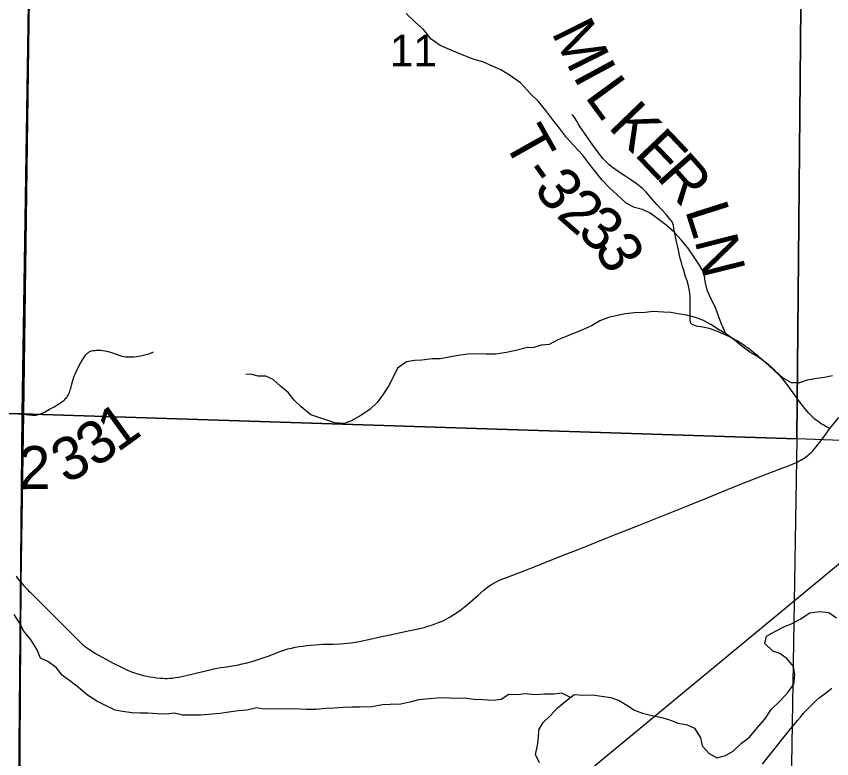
# Model space of a CAD drawing. Extents: x 0 to 34, y 0 to 22.
# Drawn here: x 3.363 to 4.44, y 19.271 to 20.252 of the extents above; entities that cross this region are included whole.
import ezdxf

# ---------------------------------------------------------------- set-up
doc = ezdxf.new("R2010")
doc.units = 0
for name, color, linetype in [('GM_X_Corporation', 7, 'Continuous'), ('GM_X_County_Road', 7, 'Continuous'), ('GM_X_Minor_River', 7, 'Continuous'), ('GM_X_Rail_Line', 7, 'Continuous'), ('GM_X_Section_Text', 7, 'Continuous'), ('GM_X_State_Route', 7, 'Continuous'), ('GM_X_Township_Road', 7, 'Continuous'), ('GM_X_Township_Road_Text', 7, 'Continuous')]:
    doc.layers.add(name, color=color, linetype=linetype)

msp = doc.modelspace()

# ---------------------------------------------------------------- linework, layer by layer
at = {"layer": 'GM_X_Corporation'}
for points in [[(5.3543, 16.3597), (5.3699, 17.5116), (5.3717, 17.6123), (4.6401, 17.6298), (4.3705, 17.6391), (4.3669, 17.8198), (4.37, 17.9048), (4.3768, 18.4091), (4.3782, 18.6502), (4.377, 18.6713), (3.7035, 18.69), (3.3642, 18.7005), (3.3691, 19.5041), (3.3724, 19.7263), (3.3869, 20.7918), (3.3886, 20.9), (2.1, 20.9), (2.1, 15.6606)], [(8.9, 20.9), (3.3886, 20.9), (3.3869, 20.7918), (3.3724, 19.7263), (3.3691, 19.5041), (3.3642, 18.7005)]]:
    msp.add_lwpolyline(points, dxfattribs=at)
for points in [[(3.3867, 20.754), (3.3708, 19.7265), (2.3578, 19.7506), (2.3781, 20.7796)], [(3.3867, 20.754), (4.4032, 20.6929), (4.3939, 19.6935), (3.3708, 19.7265)], [(5.4344, 20.6525), (5.4328, 20.6183), (5.4095, 19.6556), (4.3939, 19.6935), (4.4032, 20.6929)], [(3.3708, 19.7265), (3.3614, 18.7006), (2.3352, 18.7231), (2.3578, 19.7506)], [(4.3939, 19.6935), (4.3772, 18.6714), (3.3614, 18.7006), (3.3708, 19.7265)]]:
    msp.add_lwpolyline(points, close=True, dxfattribs=at)
at = {"layer": 'GM_X_County_Road'}
for points in [[(4.4377, 19.7069), (4.4493, 19.7218)], [(3.3693, 19.5036), (3.371, 19.5016), (3.3725, 19.4998), (3.3739, 19.4983), (3.3755, 19.4966), (3.3767, 19.4953), (3.378, 19.494), (3.3791, 19.4928), (3.3811, 19.4908), (3.3864, 19.4856), (3.3959, 19.4764), (3.4114, 19.461), (3.4372, 19.435), (3.4451, 19.427), (3.4501, 19.4224), (3.4523, 19.4205), (3.4545, 19.4188), (3.4568, 19.417), (3.4595, 19.4151), (3.463, 19.4128), (3.4669, 19.4104), (3.4771, 19.4045), (3.4908, 19.3971), (3.5036, 19.3908), (3.5109, 19.3874), (3.515, 19.3858), (3.5191, 19.3843), (3.522, 19.3833), (3.5267, 19.382), (3.5309, 19.3808), (3.5354, 19.3798), (3.5394, 19.3791), (3.5438, 19.3784), (3.5488, 19.3778), (3.5529, 19.3774), (3.5564, 19.3772), (3.5594, 19.377), (3.5622, 19.3769), (3.5656, 19.3771), (3.5691, 19.3774), (3.5732, 19.378), (3.5777, 19.3788), (3.5929, 19.3823), (3.6038, 19.3849), (3.6098, 19.3863), (3.6186, 19.3884), (3.6237, 19.3895), (3.6284, 19.3904), (3.6332, 19.3912), (3.6377, 19.3919), (3.6407, 19.3923), (3.6437, 19.3928), (3.648, 19.3935), (3.6517, 19.3941), (3.6564, 19.395), (3.6614, 19.396), (3.6662, 19.3971), (3.6711, 19.3984), (3.6746, 19.3993), (3.6783, 19.4005), (3.6836, 19.4022), (3.6889, 19.4041), (3.6968, 19.407), (3.7046, 19.41), (3.7122, 19.4128), (3.7166, 19.4144), (3.719, 19.4152), (3.7215, 19.4159), (3.724, 19.4165), (3.7264, 19.4171), (3.7313, 19.4181), (3.7366, 19.419), (3.7415, 19.4197), (3.7469, 19.4204), (3.7519, 19.421), (3.7572, 19.4214), (3.7626, 19.4217), (3.7684, 19.422), (3.7752, 19.4222), (3.7814, 19.4224), (3.7907, 19.4227), (3.7954, 19.423), (3.8001, 19.4233), (3.8047, 19.4238), (3.808, 19.4242), (3.8107, 19.4247), (3.8134, 19.4251), (3.8164, 19.4257), (3.8199, 19.4265), (3.8282, 19.4283), (3.8436, 19.4317), (3.8544, 19.4341), (3.8649, 19.4364), (3.8826, 19.4401), (3.896, 19.443), (3.9015, 19.4444), (3.9067, 19.4458), (3.9128, 19.4478), (3.9173, 19.4495), (3.9215, 19.4511), (3.9253, 19.4527), (3.9288, 19.4544), (3.9323, 19.4562), (3.9361, 19.4583), (3.9431, 19.4625), (3.9502, 19.4675), (3.959, 19.4746), (3.973, 19.487), (3.9804, 19.4935), (3.9838, 19.4963), (3.987, 19.4986), (3.9894, 19.5003), (3.9918, 19.5017), (3.9946, 19.5034), (3.9978, 19.505), (4.0005, 19.5062), (4.0034, 19.5075), (4.012, 19.5109), (4.0266, 19.5163), (4.0463, 19.524), (4.0623, 19.5305), (4.0808, 19.5379), (4.1051, 19.5474), (4.1207, 19.5536), (4.142, 19.5622), (4.1553, 19.5675), (4.1813, 19.5777), (4.1922, 19.5821), (4.2165, 19.5916), (4.2517, 19.6058), (4.2747, 19.6151), (4.3023, 19.6264), (4.3207, 19.6339), (4.3491, 19.6448), (4.3699, 19.6529), (4.385, 19.6587), (4.3899, 19.6608), (4.3942, 19.6627), (4.3967, 19.664), (4.3992, 19.6653), (4.4014, 19.6666), (4.4035, 19.6679), (4.4053, 19.6692), (4.4071, 19.6705), (4.4089, 19.6719), (4.4108, 19.6735), (4.4129, 19.6754), (4.415, 19.6777), (4.4173, 19.6802), (4.4196, 19.6829), (4.4245, 19.6892), (4.4302, 19.6966), (4.4377, 19.7069)], [(3.3627, 19.5122), (3.3642, 19.5099), (3.366, 19.5076), (3.3676, 19.5056), (3.3693, 19.5036)]]:
    msp.add_lwpolyline(points, dxfattribs=at)
at = {"layer": 'GM_X_Minor_River'}
for points in [[(4.3004, 19.8321), (4.2941, 19.846), (4.2899, 19.8569), (4.2864, 19.8671), (4.281, 19.8781), (4.2756, 19.8898), (4.2729, 19.9011), (4.2716, 19.9121), (4.2655, 19.9226), (4.2575, 19.9346), (4.2498, 19.9456), (4.241, 19.9564), (4.2319, 19.9666), (4.2208, 19.9759), (4.2105, 19.9838), (4.2003, 19.9913), (4.19, 19.9965), (4.1794, 19.999), (4.1684, 20.0049), (4.1566, 20.0158), (4.1467, 20.0248), (4.1368, 20.0353), (4.1268, 20.0477), (4.1184, 20.0582), (4.1111, 20.068), (4.0989, 20.0811), (4.0898, 20.0916), (4.0806, 20.1037), (4.0718, 20.1149), (4.0626, 20.1273), (4.0527, 20.139), (4.0428, 20.1487), (4.029, 20.1637), (4.0146, 20.1738), (4.0028, 20.1809), (3.9929, 20.1853), (3.9793, 20.1913), (3.9671, 20.1945), (3.9531, 20.2001), (3.9383, 20.2064), (3.9228, 20.213), (3.911, 20.2212), (3.9007, 20.234), (3.8896, 20.2441), (3.8778, 20.2554)], [(4.441, 19.7767), (4.4305, 19.7743), (4.4203, 19.7731), (4.4078, 19.7707), (4.3977, 19.7675), (4.3871, 19.7674), (4.376, 19.7737), (4.3646, 19.7842), (4.3536, 19.794), (4.3418, 19.8022), (4.3319, 19.8081), (4.3213, 19.8156), (4.3117, 19.8238), (4.3011, 19.8317), (4.2904, 19.838), (4.2802, 19.8443), (4.2699, 19.8503), (4.2601, 19.8536), (4.2483, 19.8569), (4.2373, 19.8587), (4.2275, 19.8601), (4.2177, 19.8607), (4.2044, 19.8614), (4.1935, 19.8605), (4.1795, 19.86), (4.167, 19.8587), (4.1572, 19.8563), (4.1451, 19.8535), (4.1338, 19.8492), (4.1226, 19.8427), (4.1109, 19.8376), (4.1011, 19.8334), (4.0913, 19.8295), (4.0781, 19.824), (4.0668, 19.8182), (4.0562, 19.817), (4.0464, 19.8142), (4.0366, 19.8134), (4.023, 19.8102), (4.0106, 19.8074), (3.9959, 19.8054), (3.9838, 19.8052), (3.972, 19.8059), (3.9596, 19.8054), (3.9467, 19.8037), (3.923, 19.7993), (3.9124, 19.7992), (3.8988, 19.7975), (3.889, 19.797), (3.8784, 19.795), (3.8667, 19.7866), (3.8608, 19.7748), (3.8552, 19.7637), (3.8478, 19.753), (3.8395, 19.7412)], [(3.8395, 19.7412), (3.8298, 19.732), (3.817, 19.7236), (3.8057, 19.7174), (3.7959, 19.7135), (3.7835, 19.7145), (3.7717, 19.7185), (3.752, 19.7251), (3.7394, 19.7356), (3.7299, 19.7446), (3.7219, 19.7548), (3.7123, 19.7626), (3.7024, 19.7716), (3.6926, 19.776), (3.6824, 19.7763), (3.6729, 19.7789), (3.6661, 19.7784)], [(4.0539, 19.2653), (4.0489, 19.2763), (4.0514, 19.2884), (4.0528, 19.2983), (4.0531, 19.3089), (4.0591, 19.3188), (4.0688, 19.328), (4.0774, 19.3376), (4.0898, 19.3479), (4.1, 19.3556), (4.1117, 19.355), (4.1242, 19.3551), (4.1359, 19.3537), (4.1484, 19.3516), (4.1594, 19.3479), (4.1693, 19.3416), (4.1795, 19.3349), (4.1901, 19.3312), (4.2023, 19.3279), (4.2155, 19.3254), (4.2273, 19.3217), (4.2371, 19.318), (4.2489, 19.3155), (4.2587, 19.3111), (4.2668, 19.2983), (4.2691, 19.2881), (4.2783, 19.2779), (4.2882, 19.272), (4.2999, 19.2751), (4.31, 19.2809), (4.3209, 19.2913), (4.3314, 19.2993), (4.3419, 19.3123), (4.3516, 19.323), (4.3602, 19.336), (4.3718, 19.3475), (4.3819, 19.3582), (4.3898, 19.3693), (4.3912, 19.3818), (4.3896, 19.3927), (4.3812, 19.4029), (4.3717, 19.41), (4.3622, 19.4129), (4.3515, 19.423), (4.3541, 19.4329), (4.3657, 19.4395), (4.3766, 19.4449), (4.3876, 19.4496), (4.3985, 19.4554), (4.4113, 19.4634), (4.4237, 19.4655), (4.4362, 19.4641), (4.4465, 19.457)], [(4.095, 19.3518), (4.0837, 19.3573), (4.0731, 19.3561), (4.0606, 19.3563), (4.0482, 19.3554), (4.0353, 19.3565), (4.0251, 19.3552), (4.0134, 19.3558), (4.0036, 19.3493), (3.9927, 19.348), (3.9798, 19.3487), (3.9673, 19.3489), (3.9556, 19.3507), (3.9412, 19.3505), (3.9288, 19.3512), (3.9189, 19.3507), (3.9087, 19.3498), (3.8948, 19.3485), (3.8827, 19.3458), (3.871, 19.343), (3.857, 19.3425), (3.8468, 19.342), (3.8325, 19.3396), (3.8173, 19.339), (3.806, 19.3389), (3.7947, 19.3384), (3.7822, 19.3375), (3.772, 19.337), (3.7592, 19.3358), (3.7463, 19.336), (3.7289, 19.3366), (3.69, 19.3362), (3.6801, 19.338), (3.6673, 19.3352), (3.6563, 19.3343), (3.6435, 19.3323), (3.6318, 19.3306), (3.6216, 19.3298), (3.6065, 19.3285), (3.5921, 19.3283), (3.5823, 19.3286), (3.5721, 19.3311), (3.5615, 19.3299), (3.549, 19.3301), (3.5369, 19.3311), (3.5263, 19.331), (3.5161, 19.3313), (3.5033, 19.3331), (3.4934, 19.3352), (3.4816, 19.3408), (3.4695, 19.3471), (3.4569, 19.3549), (3.4451, 19.365), (3.4337, 19.3736), (3.4238, 19.3807), (3.4158, 19.3913), (3.4044, 19.3991), (3.3949, 19.4035), (3.3907, 19.4149), (3.3826, 19.4273), (3.3727, 19.4393), (3.3673, 19.4502), (3.36, 19.4615)]]:
    msp.add_lwpolyline(points, dxfattribs=at)
at = {"layer": 'GM_X_Rail_Line'}
msp.add_lwpolyline([(7.1041, 20.4576), (6.548, 20.2811), (6.4552, 20.2522), (5.6204, 20.0355), (5.1742, 19.9198), (4.9387, 19.8589), (4.9007, 19.8493), (4.8622, 19.8368), (4.8204, 19.8197), (4.7961, 19.8057), (4.7682, 19.7883), (4.6322, 19.6788), (3.9277, 19.0962), (3.874, 19.0476), (3.8339, 19.0097), (3.7908, 18.9611), (3.75, 18.9158), (3.7169, 18.8748), (3.6829, 18.8279), (3.1625, 18.0833)], dxfattribs=at)
at = {"layer": 'GM_X_State_Route'}
msp.add_lwpolyline([(4.3487, 19.2637), (4.3567, 19.274), (4.3843, 19.3084), (4.395, 19.3214), (4.3986, 19.3258), (4.4024, 19.3305), (4.4071, 19.3354), (4.4114, 19.3399), (4.4158, 19.3443), (4.4196, 19.3477), (4.4235, 19.3511), (4.4281, 19.3548), (4.4337, 19.359), (4.4402, 19.3639)], dxfattribs=at)
at = {"layer": 'GM_X_Township_Road'}
for points in [[(4.4377, 19.7069), (4.4357, 19.708), (4.4323, 19.7098), (4.4289, 19.7117), (4.4261, 19.7134), (4.4233, 19.7153), (4.4207, 19.7173), (4.4177, 19.7196), (4.4151, 19.722), (4.4124, 19.7247), (4.4098, 19.7274), (4.4044, 19.7335), (4.3983, 19.7413), (4.3914, 19.7509), (4.3845, 19.7605), (4.3797, 19.7669), (4.3749, 19.7727), (4.3703, 19.7778), (4.3646, 19.7834), (4.3568, 19.7905), (4.3474, 19.7987), (4.3418, 19.8035), (4.3378, 19.8067), (4.334, 19.8098), (4.3301, 19.8128), (4.3263, 19.8155), (4.3228, 19.8179), (4.3189, 19.8204), (4.315, 19.8227), (4.3114, 19.8248), (4.3077, 19.8267), (4.3052, 19.828), (4.3024, 19.8293), (4.2994, 19.8307), (4.2964, 19.832), (4.2933, 19.8334), (4.2901, 19.8348), (4.2869, 19.8361), (4.2844, 19.8371), (4.2821, 19.838), (4.2801, 19.8386), (4.2781, 19.8392), (4.276, 19.8397), (4.2738, 19.8401), (4.2716, 19.8405), (4.2696, 19.8409), (4.2665, 19.8414), (4.2635, 19.8419), (4.2615, 19.8423), (4.2599, 19.8428), (4.2587, 19.8432), (4.2577, 19.8436), (4.2568, 19.844), (4.2561, 19.8445), (4.2553, 19.845), (4.2546, 19.8457), (4.2541, 19.8464), (4.2537, 19.8473), (4.2534, 19.8481), (4.2532, 19.849), (4.253, 19.8502), (4.2529, 19.8515), (4.253, 19.8596), (4.2532, 19.8683), (4.2532, 19.877), (4.2531, 19.8795), (4.2529, 19.882), (4.252, 19.8887), (4.2508, 19.8954), (4.249, 19.902), (4.2471, 19.9079), (4.2445, 19.9156), (4.2429, 19.9209), (4.2419, 19.9245), (4.2396, 19.9335), (4.2375, 19.9426), (4.2351, 19.9541), (4.2336, 19.9607), (4.2326, 19.965), (4.2319, 19.9686), (4.2314, 19.9719), (4.231, 19.9754), (4.2307, 19.9766), (4.2303, 19.9778), (4.2298, 19.9789), (4.2291, 19.9799), (4.2283, 19.9812), (4.2273, 19.9825), (4.2217, 19.9891), (4.2092, 20.0029), (4.1949, 20.0193), (4.19, 20.0241), (4.1858, 20.0278), (4.1819, 20.0308), (4.1747, 20.0356), (4.1679, 20.04), (4.158, 20.0465), (4.1504, 20.0519), (4.1457, 20.0559), (4.1421, 20.0593), (4.1374, 20.0643), (4.1309, 20.0726), (4.1254, 20.08), (4.1196, 20.0882), (4.1143, 20.0958), (4.1094, 20.1029), (4.1073, 20.106), (4.1051, 20.1096), (4.1036, 20.1124), (4.1025, 20.1144), (4.1013, 20.1165), (4.1004, 20.1178), (4.0995, 20.119), (4.0972, 20.1217)], [(3.3726, 19.7258), (3.3794, 19.725), (3.3843, 19.7246), (3.3865, 19.7246), (3.3886, 19.7248), (3.3905, 19.7251), (3.3925, 19.7256), (3.3943, 19.7262), (3.3962, 19.7269), (3.3981, 19.7277), (3.4, 19.7286), (3.407, 19.7325), (3.4128, 19.7359), (3.4212, 19.741), (3.423, 19.7421), (3.4246, 19.7432), (3.4262, 19.7446), (3.4275, 19.7458), (3.4286, 19.747), (3.4296, 19.7482), (3.4306, 19.7496), (3.4316, 19.7513), (3.4324, 19.7528), (3.4332, 19.7546), (3.4338, 19.7563), (3.4343, 19.758), (3.4349, 19.76), (3.4353, 19.7616), (3.436, 19.7645), (3.4375, 19.7703), (3.4385, 19.7736), (3.4394, 19.7761), (3.4405, 19.7788), (3.4419, 19.7818), (3.4434, 19.7849), (3.4482, 19.7942), (3.4504, 19.7979), (3.4525, 19.8013), (3.4542, 19.8035), (3.455, 19.8046), (3.4558, 19.8053), (3.4566, 19.8062), (3.4575, 19.8069), (3.4584, 19.8076), (3.4594, 19.8082), (3.4602, 19.8087), (3.4613, 19.8091), (3.4625, 19.8095), (3.464, 19.8099), (3.4656, 19.8101), (3.467, 19.8103), (3.4686, 19.8104), (3.4704, 19.8105), (3.4722, 19.8105), (3.4748, 19.8104), (3.4774, 19.8101), (3.4799, 19.8097), (3.4824, 19.8091), (3.4875, 19.8077), (3.5009, 19.8031), (3.503, 19.8026), (3.5053, 19.8021), (3.5071, 19.8018), (3.509, 19.8017), (3.5111, 19.8016), (3.5134, 19.8016), (3.5158, 19.8016), (3.5184, 19.8018), (3.5213, 19.8022), (3.5241, 19.8026), (3.527, 19.8031), (3.5292, 19.8035), (3.531, 19.8039), (3.5328, 19.8043), (3.5345, 19.8048), (3.5361, 19.8052), (3.5379, 19.8058), (3.5394, 19.8063), (3.541, 19.8069), (3.5426, 19.8075), (3.5441, 19.8082)], [(3.2519, 19.7277), (3.258, 19.7299), (3.2612, 19.7303), (3.2638, 19.7305), (3.2662, 19.7305), (3.273, 19.7304), (3.3028, 19.729), (3.339, 19.7273), (3.3529, 19.7268), (3.3591, 19.7268), (3.3655, 19.7264), (3.3726, 19.7258)]]:
    msp.add_lwpolyline(points, dxfattribs=at)

# ---------------------------------------------------------------- texts
at = {"layer": 'GM_X_Section_Text'}
msp.add_text('11', height=0.04186, rotation=0, dxfattribs=at).set_placement((3.8563, 20.1853))
at = {"layer": 'GM_X_Township_Road_Text'}
for s, rotation, p in [('M', 296.4416, (4.0691, 20.2301)), ('I', 298.409, (4.0975, 20.173)), ('L', 306.2023, (4.113, 20.1455)), ('K', 313.8966, (4.1434, 20.1049)), ('T', 299.3462, (4.0052, 20.087)), ('E', 313.668, (4.178, 20.0689)), ('R', 311.6767, (4.207, 20.0386)), ('-', 305.5239, (4.0297, 20.0443)), ('3', 308.6235, (4.0452, 20.0227)), ('2', 318.9899, (4.0748, 19.9872)), ('L', 287.6293, (4.2459, 19.9955)), ('3', 320.0967, (4.1021, 19.9635)), ('3', 298.8754, (4.1255, 19.9453)), ('N', 284.1007, (4.2586, 19.9559)), ('1', 35.9276, (3.4967, 19.6747)), ('3', 35.1911, (3.4674, 19.6541)), ('3', 26.2489, (3.4277, 19.6336)), ('2', 0.7608, (3.3662, 19.6268))]:
    msp.add_text(s, height=0.0568, rotation=rotation, dxfattribs=at).set_placement(p)

doc.saveas('drawing.dxf')
